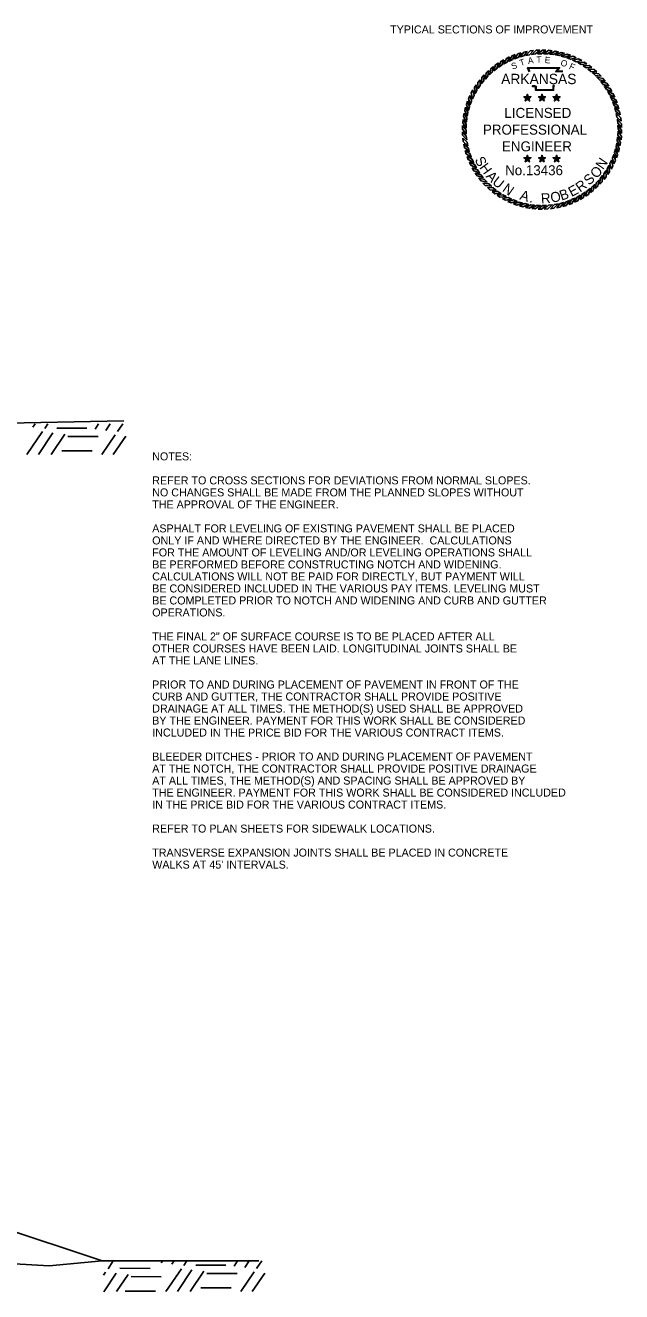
# Model space of a CAD drawing. Extents: x 1001270 to 1003428, y 1840152 to 1842912.
# Drawn here: x 1001383.8 to 1001428.5, y 1840713.8 to 1840808.7 of the extents above; entities that cross this region are included whole.
import ezdxf

# ---------------------------------------------------------------- set-up
doc = ezdxf.new("R2010")
doc.units = 0
for name, color, linetype in [('1', 7, 'Continuous'), ('19', 7, 'Continuous'), ('G-ANNO-SYMB', 7, 'Continuous')]:
    doc.layers.add(name, color=color, linetype=linetype)

msp = doc.modelspace()

# ---------------------------------------------------------------- linework, layer by layer
at = {"layer": '19'}
for p, q in [((1001384.372, 1840778.578), (1001384.538, 1840778.822)), ((1001385.268, 1840778.486), (1001385.493, 1840778.825)), ((1001389.032, 1840778.43), (1001389.293, 1840778.826)), ((1001389.826, 1840778.339), (1001390.158, 1840778.827)), ((1001390.722, 1840778.246), (1001391.102, 1840778.82)), ((1001383.93, 1840776.523), (1001385.082, 1840778.244)), ((1001384.784, 1840776.525), (1001385.877, 1840778.152)), ((1001385.739, 1840776.527), (1001386.772, 1840778.06)), ((1001386.155, 1840778.515), (1001388.416, 1840778.504)), ((1001386.985, 1840777.887), (1001389.256, 1840777.875)), ((1001389.54, 1840776.528), (1001390.536, 1840778.004)), ((1001390.394, 1840776.531), (1001391.331, 1840777.912)), ((1001386.543, 1840776.817), (1001388.803, 1840776.795)), ((1001389.561, 1840716.078), (1001376.273, 1840720.508)), ((1001389.663, 1840715.026), (1001389.817, 1840715.252)), ((1001390.003, 1840715.494), (1001390.394, 1840716.077)), ((1001390.891, 1840715.533), (1001393.151, 1840715.512)), ((1001393.988, 1840715.928), (1001394.094, 1840716.078)), ((1001394.34, 1840713.781), (1001395.492, 1840715.502)), ((1001394.783, 1840715.837), (1001394.949, 1840716.081)), ((1001395.195, 1840713.784), (1001396.287, 1840715.41)), ((1001395.678, 1840715.744), (1001395.904, 1840716.083)), ((1001396.15, 1840713.786), (1001397.182, 1840715.318)), ((1001396.566, 1840715.774), (1001398.826, 1840715.762)), ((1001399.442, 1840715.689), (1001399.704, 1840716.084)), ((1001399.95, 1840713.787), (1001400.946, 1840715.263)), ((1001400.237, 1840715.597), (1001400.569, 1840716.086)), ((1001401.132, 1840715.505), (1001401.513, 1840716.079)), ((1001389.685, 1840713.778), (1001390.612, 1840715.16)), ((1001390.64, 1840713.78), (1001391.507, 1840715.068)), ((1001391.731, 1840714.904), (1001393.991, 1840714.883)), ((1001397.396, 1840715.145), (1001399.666, 1840715.133)), ((1001400.805, 1840713.789), (1001401.741, 1840715.171)), ((1001391.278, 1840713.825), (1001393.549, 1840713.812)), ((1001396.954, 1840714.075), (1001399.214, 1840714.054))]:
    msp.add_line(p, q, dxfattribs=at)
for points in [[(1001337.671, 1840780.372), (1001352.835, 1840780.728), (1001364.846, 1840780.388), (1001369.035, 1840779.851), (1001372.746, 1840778.779), (1001376.583, 1840778.814), (1001379.984, 1840778.819), (1001391.176, 1840779.066)], [(1001340.526, 1840717.523), (1001352.785, 1840717.913), (1001369.502, 1840717.58), (1001373.538, 1840717.411), (1001379.955, 1840716.041), (1001385.579, 1840715.706), (1001389.561, 1840716.078), (1001401.29, 1840716.079)]]:
    msp.add_lwpolyline(points, dxfattribs=at)
at = {"layer": 'G-ANNO-SYMB'}
for points in [[(1001420.071, 1840806.328), (1001419.84, 1840806.218), (1001419.646, 1840805.803), (1001419.889, 1840805.937)], [(1001420.506, 1840806.502), (1001420.266, 1840806.411), (1001420.041, 1840806.013), (1001420.294, 1840806.127)], [(1001420.953, 1840806.642), (1001420.707, 1840806.57), (1001420.451, 1840806.191), (1001420.712, 1840806.285)], [(1001421.41, 1840806.747), (1001421.159, 1840806.694), (1001420.874, 1840806.336), (1001421.141, 1840806.409)], [(1001421.873, 1840806.815), (1001421.619, 1840806.782), (1001421.307, 1840806.448), (1001421.579, 1840806.5)], [(1001422.341, 1840806.847), (1001422.084, 1840806.834), (1001421.747, 1840806.525), (1001422.023, 1840806.555)], [(1001422.809, 1840806.842), (1001422.552, 1840806.849), (1001422.192, 1840806.568), (1001422.469, 1840806.576)], [(1001423.276, 1840806.8), (1001423.02, 1840806.827), (1001422.639, 1840806.575), (1001422.916, 1840806.562)], [(1001423.737, 1840806.722), (1001423.485, 1840806.769), (1001423.085, 1840806.547), (1001423.36, 1840806.513)], [(1001424.192, 1840806.608), (1001423.944, 1840806.675), (1001423.528, 1840806.485), (1001423.799, 1840806.429)], [(1001424.636, 1840806.458), (1001424.394, 1840806.544), (1001423.964, 1840806.388), (1001424.23, 1840806.311)], [(1001425.066, 1840806.274), (1001424.832, 1840806.379), (1001424.392, 1840806.257), (1001424.651, 1840806.159)], [(1001418.868, 1840805.608), (1001418.668, 1840805.447), (1001418.577, 1840804.998), (1001418.782, 1840805.185)], [(1001419.25, 1840805.879), (1001419.038, 1840805.734), (1001418.912, 1840805.294), (1001419.131, 1840805.464)], [(1001419.652, 1840806.119), (1001419.429, 1840805.992), (1001419.269, 1840805.563), (1001419.501, 1840805.716)], [(1001425.482, 1840806.057), (1001425.256, 1840806.18), (1001424.808, 1840806.093), (1001425.058, 1840805.975)], [(1001425.878, 1840805.808), (1001425.664, 1840805.948), (1001425.209, 1840805.896), (1001425.45, 1840805.759)], [(1001426.254, 1840805.529), (1001426.051, 1840805.685), (1001425.594, 1840805.669), (1001425.823, 1840805.514)], [(1001426.607, 1840805.221), (1001426.417, 1840805.393), (1001425.96, 1840805.413), (1001426.177, 1840805.239)], [(1001417.866, 1840804.627), (1001417.709, 1840804.423), (1001417.725, 1840803.966), (1001417.881, 1840804.196)], [(1001418.174, 1840804.979), (1001418.002, 1840804.789), (1001417.982, 1840804.332), (1001418.155, 1840804.549)], [(1001418.508, 1840805.307), (1001418.322, 1840805.131), (1001418.266, 1840804.677), (1001418.456, 1840804.879)], [(1001426.935, 1840804.886), (1001426.759, 1840805.072), (1001426.305, 1840805.128), (1001426.507, 1840804.938)], [(1001427.235, 1840804.526), (1001427.074, 1840804.726), (1001426.626, 1840804.817), (1001426.813, 1840804.612)], [(1001427.507, 1840804.145), (1001427.362, 1840804.356), (1001426.922, 1840804.482), (1001427.092, 1840804.263)], [(1001417.337, 1840803.854), (1001417.214, 1840803.629), (1001417.302, 1840803.18), (1001417.419, 1840803.431)], [(1001417.586, 1840804.251), (1001417.446, 1840804.036), (1001417.498, 1840803.581), (1001417.635, 1840803.822)], [(1001421.42, 1840803.259), (1001421.481, 1840803.343), (1001421.42, 1840803.532), (1001421.359, 1840803.343)], [(1001422.511, 1840803.259), (1001422.572, 1840803.343), (1001422.511, 1840803.532), (1001422.45, 1840803.343)], [(1001423.602, 1840803.259), (1001423.663, 1840803.343), (1001423.602, 1840803.532), (1001423.541, 1840803.343)], [(1001427.747, 1840803.743), (1001427.619, 1840803.965), (1001427.191, 1840804.125), (1001427.343, 1840803.894)], [(1001427.955, 1840803.323), (1001427.845, 1840803.555), (1001427.431, 1840803.748), (1001427.565, 1840803.505)], [(1001416.787, 1840802.564), (1001416.72, 1840802.316), (1001416.909, 1840801.9), (1001416.966, 1840802.172)], [(1001416.936, 1840803.008), (1001416.85, 1840802.766), (1001417.006, 1840802.337), (1001417.084, 1840802.603)], [(1001417.12, 1840803.439), (1001417.015, 1840803.205), (1001417.137, 1840802.764), (1001417.235, 1840803.023)], [(1001421.42, 1840803.259), (1001421.359, 1840803.343), (1001421.161, 1840803.343), (1001421.321, 1840803.227)], [(1001421.42, 1840803.259), (1001421.321, 1840803.227), (1001421.26, 1840803.038), (1001421.42, 1840803.155)], [(1001421.42, 1840803.259), (1001421.519, 1840803.227), (1001421.68, 1840803.343), (1001421.481, 1840803.343)], [(1001421.42, 1840803.259), (1001421.42, 1840803.155), (1001421.58, 1840803.038), (1001421.519, 1840803.227)], [(1001422.511, 1840803.259), (1001422.45, 1840803.343), (1001422.252, 1840803.343), (1001422.412, 1840803.227)], [(1001422.511, 1840803.259), (1001422.412, 1840803.227), (1001422.351, 1840803.038), (1001422.511, 1840803.155)], [(1001422.511, 1840803.259), (1001422.61, 1840803.227), (1001422.77, 1840803.343), (1001422.572, 1840803.343)], [(1001422.511, 1840803.259), (1001422.511, 1840803.155), (1001422.671, 1840803.038), (1001422.61, 1840803.227)], [(1001423.602, 1840803.259), (1001423.541, 1840803.343), (1001423.343, 1840803.343), (1001423.503, 1840803.227)], [(1001423.602, 1840803.259), (1001423.503, 1840803.227), (1001423.442, 1840803.038), (1001423.602, 1840803.155)], [(1001423.602, 1840803.259), (1001423.701, 1840803.227), (1001423.861, 1840803.343), (1001423.663, 1840803.343)], [(1001423.602, 1840803.259), (1001423.602, 1840803.155), (1001423.762, 1840803.038), (1001423.701, 1840803.227)], [(1001428.13, 1840802.888), (1001428.039, 1840803.128), (1001427.641, 1840803.353), (1001427.755, 1840803.101)], [(1001428.27, 1840802.441), (1001428.198, 1840802.687), (1001427.819, 1840802.943), (1001427.913, 1840802.682)], [(1001416.594, 1840801.648), (1001416.567, 1840801.393), (1001416.819, 1840801.011), (1001416.832, 1840801.288)], [(1001416.672, 1840802.11), (1001416.625, 1840801.857), (1001416.847, 1840801.457), (1001416.882, 1840801.732)], [(1001428.374, 1840801.985), (1001428.322, 1840802.236), (1001427.964, 1840802.52), (1001428.037, 1840802.253)], [(1001428.443, 1840801.521), (1001428.41, 1840801.776), (1001428.075, 1840802.087), (1001428.127, 1840801.815)], [(1001428.475, 1840801.054), (1001428.462, 1840801.31), (1001428.153, 1840801.647), (1001428.183, 1840801.372)], [(1001416.553, 1840801.181), (1001416.545, 1840800.925), (1001416.827, 1840800.564), (1001416.818, 1840800.841)], [(1001416.548, 1840800.713), (1001416.56, 1840800.456), (1001416.869, 1840800.119), (1001416.839, 1840800.395)], [(1001428.428, 1840800.119), (1001428.455, 1840800.374), (1001428.203, 1840800.755), (1001428.19, 1840800.478)], [(1001428.47, 1840800.585), (1001428.477, 1840800.842), (1001428.195, 1840801.202), (1001428.204, 1840800.925)], [(1001416.579, 1840800.245), (1001416.612, 1840799.991), (1001416.947, 1840799.679), (1001416.895, 1840799.951)], [(1001416.648, 1840799.782), (1001416.7, 1840799.531), (1001417.058, 1840799.246), (1001416.985, 1840799.514)], [(1001428.235, 1840799.203), (1001428.302, 1840799.45), (1001428.113, 1840799.866), (1001428.057, 1840799.595)], [(1001428.35, 1840799.657), (1001428.397, 1840799.909), (1001428.175, 1840800.309), (1001428.141, 1840800.034)], [(1001416.752, 1840799.325), (1001416.824, 1840799.079), (1001417.204, 1840798.823), (1001417.11, 1840799.084)], [(1001416.892, 1840798.878), (1001416.983, 1840798.639), (1001417.381, 1840798.413), (1001417.267, 1840798.666)], [(1001421.42, 1840798.691), (1001421.359, 1840798.775), (1001421.161, 1840798.775), (1001421.321, 1840798.658)], [(1001421.42, 1840798.691), (1001421.481, 1840798.775), (1001421.42, 1840798.963), (1001421.359, 1840798.775)], [(1001421.42, 1840798.691), (1001421.519, 1840798.658), (1001421.68, 1840798.775), (1001421.481, 1840798.775)], [(1001422.511, 1840798.691), (1001422.45, 1840798.775), (1001422.252, 1840798.775), (1001422.412, 1840798.658)], [(1001422.511, 1840798.691), (1001422.572, 1840798.775), (1001422.511, 1840798.963), (1001422.45, 1840798.775)], [(1001422.511, 1840798.691), (1001422.61, 1840798.658), (1001422.77, 1840798.775), (1001422.572, 1840798.775)], [(1001423.602, 1840798.691), (1001423.541, 1840798.775), (1001423.343, 1840798.775), (1001423.503, 1840798.658)], [(1001423.602, 1840798.691), (1001423.663, 1840798.775), (1001423.602, 1840798.963), (1001423.541, 1840798.775)], [(1001423.602, 1840798.691), (1001423.701, 1840798.658), (1001423.861, 1840798.775), (1001423.663, 1840798.775)], [(1001427.902, 1840798.328), (1001428.007, 1840798.562), (1001427.885, 1840799.003), (1001427.787, 1840798.743)], [(1001428.086, 1840798.759), (1001428.172, 1840799), (1001428.016, 1840799.43), (1001427.938, 1840799.164)], [(1001417.067, 1840798.444), (1001417.177, 1840798.212), (1001417.591, 1840798.019), (1001417.457, 1840798.261)], [(1001417.275, 1840798.024), (1001417.403, 1840797.801), (1001417.831, 1840797.641), (1001417.679, 1840797.873)], [(1001421.42, 1840798.691), (1001421.321, 1840798.658), (1001421.26, 1840798.47), (1001421.42, 1840798.587)], [(1001421.42, 1840798.691), (1001421.42, 1840798.587), (1001421.58, 1840798.47), (1001421.519, 1840798.658)], [(1001422.511, 1840798.691), (1001422.412, 1840798.658), (1001422.351, 1840798.47), (1001422.511, 1840798.587)], [(1001422.511, 1840798.691), (1001422.511, 1840798.587), (1001422.671, 1840798.47), (1001422.61, 1840798.658)], [(1001423.602, 1840798.691), (1001423.503, 1840798.658), (1001423.442, 1840798.47), (1001423.602, 1840798.587)], [(1001423.602, 1840798.691), (1001423.602, 1840798.587), (1001423.762, 1840798.47), (1001423.701, 1840798.658)], [(1001427.156, 1840797.14), (1001427.313, 1840797.343), (1001427.297, 1840797.8), (1001427.141, 1840797.571)], [(1001427.436, 1840797.516), (1001427.576, 1840797.731), (1001427.524, 1840798.185), (1001427.387, 1840797.944)], [(1001427.685, 1840797.913), (1001427.808, 1840798.138), (1001427.721, 1840798.587), (1001427.603, 1840798.336)], [(1001417.515, 1840797.622), (1001417.66, 1840797.41), (1001418.1, 1840797.284), (1001417.93, 1840797.503)], [(1001417.787, 1840797.24), (1001417.948, 1840797.04), (1001418.396, 1840796.949), (1001418.209, 1840797.154)], [(1001418.087, 1840796.881), (1001418.263, 1840796.694), (1001418.717, 1840796.638), (1001418.515, 1840796.828)], [(1001426.514, 1840796.459), (1001426.7, 1840796.635), (1001426.756, 1840797.089), (1001426.566, 1840796.887)], [(1001426.848, 1840796.787), (1001427.021, 1840796.977), (1001427.04, 1840797.434), (1001426.867, 1840797.218)], [(1001418.415, 1840796.546), (1001418.605, 1840796.374), (1001419.062, 1840796.354), (1001418.846, 1840796.527)], [(1001418.768, 1840796.238), (1001418.971, 1840796.081), (1001419.428, 1840796.097), (1001419.199, 1840796.253)], [(1001419.144, 1840795.958), (1001419.359, 1840795.818), (1001419.813, 1840795.87), (1001419.572, 1840796.007)], [(1001424.951, 1840795.439), (1001425.183, 1840795.549), (1001425.376, 1840795.963), (1001425.133, 1840795.83)], [(1001425.37, 1840795.647), (1001425.593, 1840795.775), (1001425.753, 1840796.203), (1001425.521, 1840796.051)], [(1001425.772, 1840795.888), (1001425.984, 1840796.032), (1001426.11, 1840796.472), (1001425.891, 1840796.302)], [(1001426.154, 1840796.159), (1001426.354, 1840796.32), (1001426.445, 1840796.768), (1001426.24, 1840796.581)], [(1001419.54, 1840795.709), (1001419.766, 1840795.586), (1001420.215, 1840795.674), (1001419.964, 1840795.792)], [(1001419.956, 1840795.492), (1001420.19, 1840795.387), (1001420.63, 1840795.51), (1001420.371, 1840795.608)], [(1001420.386, 1840795.308), (1001420.628, 1840795.222), (1001421.058, 1840795.379), (1001420.792, 1840795.456)], [(1001420.83, 1840795.159), (1001421.078, 1840795.092), (1001421.494, 1840795.282), (1001421.223, 1840795.338)], [(1001421.285, 1840795.045), (1001421.537, 1840794.997), (1001421.937, 1840795.219), (1001421.662, 1840795.254)], [(1001421.747, 1840794.966), (1001422.002, 1840794.939), (1001422.383, 1840795.191), (1001422.106, 1840795.204)], [(1001422.213, 1840794.925), (1001422.47, 1840794.917), (1001422.83, 1840795.199), (1001422.553, 1840795.19)], [(1001422.682, 1840794.92), (1001422.938, 1840794.933), (1001423.275, 1840795.241), (1001422.999, 1840795.211)], [(1001423.149, 1840794.951), (1001423.403, 1840794.984), (1001423.715, 1840795.319), (1001423.443, 1840795.267)], [(1001423.612, 1840795.02), (1001423.863, 1840795.073), (1001424.148, 1840795.43), (1001423.881, 1840795.357)], [(1001424.069, 1840795.124), (1001424.315, 1840795.197), (1001424.571, 1840795.576), (1001424.31, 1840795.482)], [(1001424.516, 1840795.264), (1001424.756, 1840795.356), (1001424.981, 1840795.754), (1001424.728, 1840795.64)]]:
    msp.add_lwpolyline(points, close=True, dxfattribs=at)
for points in [[(1001421.555, 1840805.213), (1001421.416, 1840805.514), (1001423.823, 1840805.516), (1001423.621, 1840805.263), (1001423.785, 1840805.265), (1001423.922, 1840805.267), (1001424.058, 1840805.252)], [(1001421.59, 1840805.229), (1001421.476, 1840805.476), (1001423.743, 1840805.478), (1001423.542, 1840805.224), (1001423.785, 1840805.227), (1001423.92, 1840805.229), (1001424.054, 1840805.214)], [(1001423.443, 1840804.205), (1001423.402, 1840804.171), (1001423.389, 1840804.121), (1001423.375, 1840803.997), (1001423.375, 1840803.83), (1001422.032, 1840803.83), (1001422.032, 1840804.055), (1001422.032, 1840804.105), (1001421.977, 1840804.121), (1001421.786, 1840804.121), (1001421.752, 1840804.173)], [(1001423.419, 1840804.234), (1001423.369, 1840804.193), (1001423.351, 1840804.129), (1001423.337, 1840803.999), (1001423.337, 1840803.869), (1001422.07, 1840803.869), (1001422.07, 1840804.055), (1001422.07, 1840804.133), (1001421.983, 1840804.16), (1001421.807, 1840804.16), (1001421.784, 1840804.194)]]:
    msp.add_lwpolyline(points, dxfattribs=at)

# ---------------------------------------------------------------- texts
at = {"layer": '1'}
msp.add_text('TYPICAL SECTIONS OF IMPROVEMENT', height=0.6, dxfattribs=at).set_placement((1001411.131, 1840808.092))
at = {"layer": '19'}
for s, p in [('NOTES:', (1001393.311, 1840776.09)), ('REFER TO CROSS SECTIONS FOR DEVIATIONS FROM NORMAL SLOPES.', (1001393.311, 1840774.29)), ('NO CHANGES SHALL BE MADE FROM THE PLANNED SLOPES WITHOUT', (1001393.311, 1840773.39)), ('THE APPROVAL OF THE ENGINEER.', (1001393.311, 1840772.49)), ('ASPHALT FOR LEVELING OF EXISTING PAVEMENT SHALL BE PLACED', (1001393.311, 1840770.69)), ('ONLY IF AND WHERE DIRECTED BY THE ENGINEER.  CALCULATIONS', (1001393.311, 1840769.79)), ('FOR THE AMOUNT OF LEVELING AND/OR LEVELING OPERATIONS SHALL', (1001393.311, 1840768.89)), ('BE PERFORMED BEFORE CONSTRUCTING NOTCH AND WIDENING.', (1001393.311, 1840767.99)), ('CALCULATIONS WILL NOT BE PAID FOR DIRECTLY, BUT PAYMENT WILL', (1001393.311, 1840767.09)), ('BE CONSIDERED INCLUDED IN THE VARIOUS PAY ITEMS. LEVELING MUST ', (1001393.311, 1840766.19)), ('BE COMPLETED PRIOR TO NOTCH AND WIDENING AND CURB AND GUTTER', (1001393.311, 1840765.29)), ('OPERATIONS. ', (1001393.311, 1840764.39)), ('THE FINAL 2" OF SURFACE COURSE IS TO BE PLACED AFTER ALL', (1001393.311, 1840762.59)), ('OTHER COURSES HAVE BEEN LAID. LONGITUDINAL JOINTS SHALL BE', (1001393.311, 1840761.69)), ('AT THE LANE LINES.', (1001393.311, 1840760.79)), ('PRIOR TO AND DURING PLACEMENT OF PAVEMENT IN FRONT OF THE', (1001393.311, 1840758.99)), ('CURB AND GUTTER, THE CONTRACTOR SHALL PROVIDE POSITIVE', (1001393.311, 1840758.09)), ('DRAINAGE AT ALL TIMES. THE METHOD(S) USED SHALL BE APPROVED', (1001393.311, 1840757.19)), ('BY THE ENGINEER. PAYMENT FOR THIS WORK SHALL BE CONSIDERED', (1001393.311, 1840756.29)), ('INCLUDED IN THE PRICE BID FOR THE VARIOUS CONTRACT ITEMS.', (1001393.311, 1840755.39)), ('BLEEDER DITCHES - PRIOR TO AND DURING PLACEMENT OF PAVEMENT', (1001393.311, 1840753.59)), ('AT THE NOTCH, THE CONTRACTOR SHALL PROVIDE POSITIVE DRAINAGE', (1001393.311, 1840752.69)), ('AT ALL TIMES, THE METHOD(S) AND SPACING SHALL BE APPROVED BY', (1001393.311, 1840751.79)), ('THE ENGINEER. PAYMENT FOR THIS WORK SHALL BE CONSIDERED INCLUDED', (1001393.311, 1840750.89)), ('IN THE PRICE BID FOR THE VARIOUS CONTRACT ITEMS.', (1001393.311, 1840749.99)), ('REFER TO PLAN SHEETS FOR SIDEWALK LOCATIONS.', (1001393.311, 1840748.19)), ('TRANSVERSE EXPANSION JOINTS SHALL BE PLACED IN CONCRETE', (1001393.311, 1840746.39)), ("WALKS AT 45' INTERVALS.", (1001393.311, 1840745.49))]:
    msp.add_text(s, height=0.6, dxfattribs=at).set_placement(p)
at = {"layer": 'G-ANNO-SYMB'}
for s, height, rotation, p in [('T', 0.475, 1.47887, (1001422.095, 1840805.887)), ('E', 0.475, 356.67203, (1001422.702, 1840805.873)), ('S', 0.475, 19.77256, (1001420.302, 1840805.371)), ('T', 0.475, 16.90148, (1001420.906, 1840805.642)), ('A', 0.475, 8.67877, (1001421.482, 1840805.793)), ('O', 0.475, 341.2218, (1001423.855, 1840805.71)), ('F', 0.475, 335.36282, (1001424.495, 1840805.46)), ('ARKANSAS', 0.7747, 360, (1001419.449, 1840804.291)), ('LICENSED', 0.75, 360, (1001419.69, 1840801.763)), ('PROFESSIONAL', 0.75, 360, (1001418.082, 1840800.508)), ('ENGINEER', 0.75, 360, (1001419.511, 1840799.254)), ('S', 0.75, 298.16364, (1001417.443, 1840798.623)), ('N', 0.75, 56.10067, (1001427.085, 1840797.84)), ('H', 0.75, 305.61905, (1001417.785, 1840798.036)), ('No.13436', 0.747, 360, (1001419.748, 1840797.466)), ('O', 0.75, 44.77573, (1001426.564, 1840797.164)), ('A', 0.75, 313.44722, (1001418.261, 1840797.351)), ('U', 0.75, 320.90262, (1001418.729, 1840796.862)), ('N', 0.75, 324.93262, (1001419.485, 1840796.303)), ('R', 0.75, 35.65967, (1001425.359, 1840796.157)), ('S', 0.75, 43.48784, (1001426.049, 1840796.667)), ('A', 0.75, 343.09908, (1001420.792, 1840795.66)), ('R', 0.75, 3.22866, (1001422.449, 1840795.347)), ('O', 0.75, 11.42961, (1001423.216, 1840795.395)), ('B', 0.75, 18.88501, (1001423.968, 1840795.554)), ('E', 0.75, 27.83149, (1001424.725, 1840795.825)), ('.', 0.75, 351.30002, (1001421.529, 1840795.441))]:
    msp.add_text(s, height=height, rotation=rotation, dxfattribs=at).set_placement(p)

doc.saveas('drawing.dxf')
